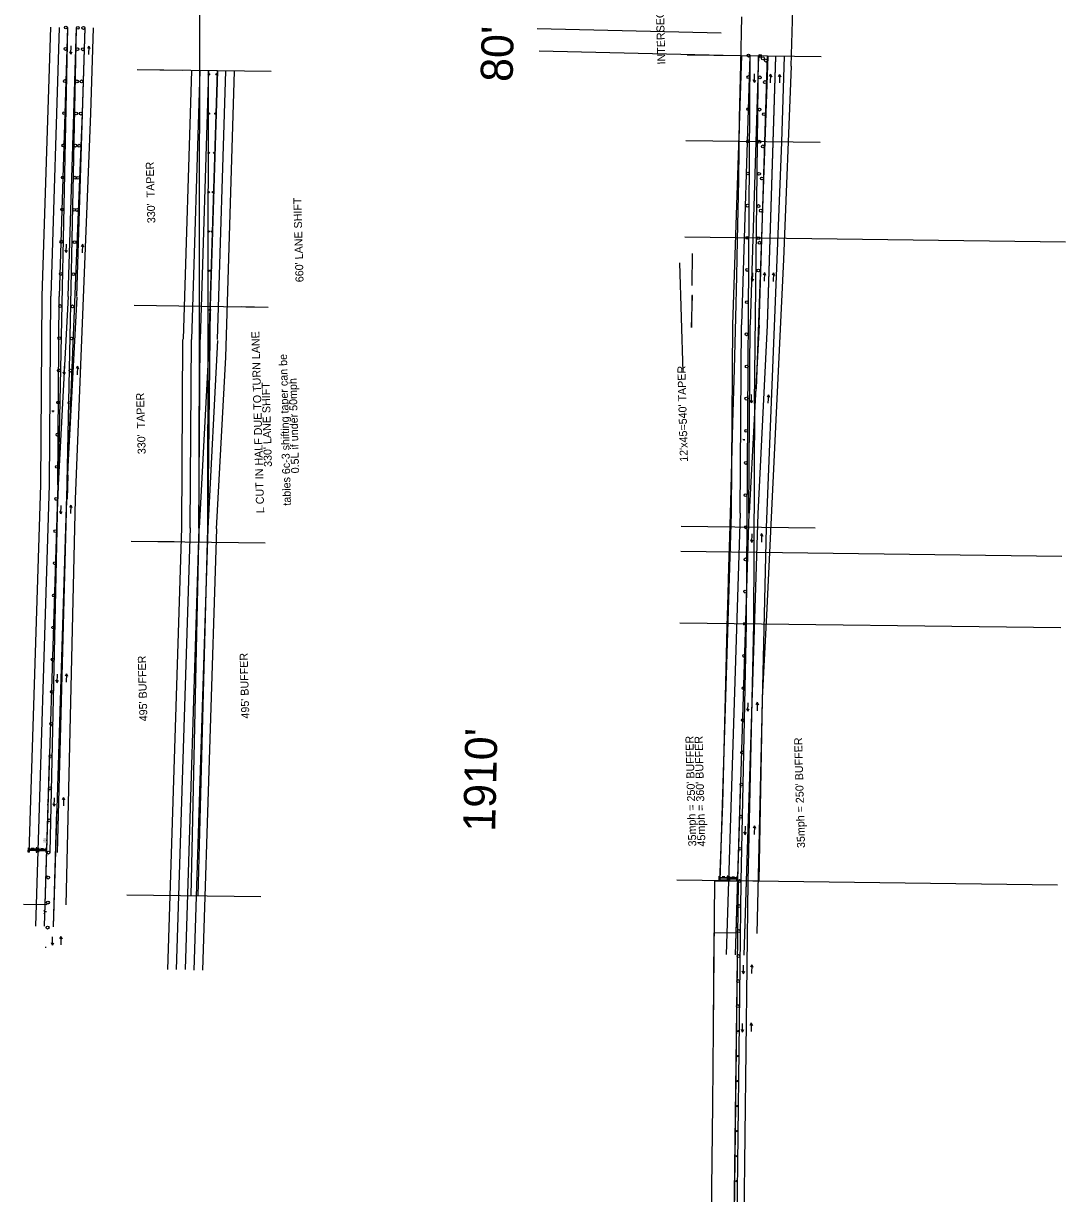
# Model space of a CAD drawing. Extents: x 1651568 to 1653044, y 601329 to 611807.
# Drawn here: x 1651568 to 1653027, y 608161 to 609799 of the extents above; entities that cross this region are included whole.
import ezdxf

# ---------------------------------------------------------------- set-up
doc = ezdxf.new("R2010")
doc.units = 0
for name, color, linetype in [('CM_Corridor_Design', 7, 'Continuous'), ('Default', 7, 'Continuous'), ('DR_X_Storm_Sewer', 7, 'Continuous'), ('DT_X_Break_Line', 7, 'Continuous'), ('DT_X_Contour_Major', 7, 'Continuous'), ('DT_X_Void', 7, 'Continuous'), ('GE_P_Alignment_500_Cardinal_Points', 7, 'Continuous'), ('GE_P_Alignment_500_Distances', 7, 'Continuous'), ('GE_P_Alignment_500_Stations', 7, 'Continuous'), ('PF_P_Grade_Line', 7, 'Continuous'), ('PF_X_Ground_Line', 7, 'Continuous'), ('PF_X_Ground_Line_LT', 7, 'Continuous'), ('PF_X_Ground_Line_RT', 7, 'Continuous'), ('PV_P_EOP', 7, 'Continuous'), ('PV_X_EOP', 7, 'Continuous'), ('RW_X_Esmt_LA', 7, 'Continuous'), ('SC_ProfileRun1', 7, 'Continuous'), ('SC_ProfileRun2', 7, 'Continuous'), ('SC_Scratch3', 7, 'Continuous')]:
    doc.layers.add(name, color=color, linetype=linetype)

msp = doc.modelspace()

# ---------------------------------------------------------------- linework, layer by layer
at = {"layer": 'CM_Corridor_Design'}
for p, q in [((1651634.4, 609755.7), (1651634.7, 609767.6)), ((1651659.4, 609767.2), (1651657.6, 609763.9)), ((1651659.4, 609767.2), (1651659, 609755.3)), ((1651659.4, 609767.2), (1651661, 609763.8)), ((1651634.4, 609755.7), (1651632.8, 609759.1)), ((1651634.4, 609755.7), (1651636.2, 609759)), ((1652591.3, 609716.3), (1652589.6, 609719.7)), ((1652591.3, 609716.3), (1652591.6, 609728.1)), ((1652591.3, 609716.3), (1652593.1, 609719.6)), ((1652613.9, 609727.8), (1652612.1, 609724.4)), ((1652613.9, 609727.8), (1652613.5, 609715.9)), ((1652613.9, 609727.8), (1652615.5, 609724.3)), ((1652626.5, 609727.4), (1652624.7, 609724)), ((1652626.5, 609727.4), (1652626.2, 609715.5)), ((1652626.5, 609727.4), (1652628.1, 609723.9)), ((1651627.9, 609478.2), (1651628.3, 609490)), ((1651650.7, 609489.7), (1651648.9, 609486.3)), ((1651650.7, 609489.7), (1651650.3, 609477.8)), ((1651650.7, 609489.7), (1651652.3, 609486.2)), ((1651627.9, 609478.2), (1651626.3, 609481.6)), ((1651627.9, 609478.2), (1651629.8, 609481.5)), ((1652588.7, 609438), (1652587, 609441.4)), ((1652588.7, 609438), (1652589, 609449.8)), ((1652588.7, 609438), (1652590.5, 609441.3)), ((1652605.3, 609450.1), (1652603.5, 609446.7)), ((1652605.3, 609450.1), (1652604.9, 609438.2)), ((1652605.3, 609450.1), (1652606.9, 609446.6)), ((1652617.9, 609449.7), (1652616.1, 609446.4)), ((1652617.9, 609449.7), (1652617.6, 609437.8)), ((1652617.9, 609449.7), (1652619.5, 609446.3)), ((1651625.1, 609307.3), (1651623.5, 609310.7)), ((1651625.1, 609307.3), (1651625.5, 609319.1)), ((1651625.1, 609307.3), (1651627, 609310.6)), ((1651643.8, 609319), (1651641.9, 609315.7)), ((1651643.8, 609319), (1651643.1, 609307.2)), ((1651643.8, 609319), (1651645.3, 609315.5)), ((1652587, 609267.8), (1652587.4, 609279.6)), ((1652611, 609279.2), (1652609, 609275.9)), ((1652611, 609279.2), (1652610.2, 609267.3)), ((1652611, 609279.2), (1652612.5, 609275.7)), ((1652587, 609267.8), (1652585.4, 609271.2)), ((1652587, 609267.8), (1652588.9, 609271.1)), ((1651620.6, 609112.4), (1651619, 609115.8)), ((1651620.6, 609112.4), (1651621, 609124.3)), ((1651620.6, 609112.4), (1651622.4, 609115.7)), ((1651634.2, 609124.6), (1651632.5, 609121.3)), ((1651634.2, 609124.6), (1651634.1, 609112.8)), ((1651634.2, 609124.6), (1651635.9, 609121.2)), ((1652587.8, 609072.6), (1652588.1, 609084.4)), ((1652601.4, 609084.8), (1652599.6, 609081.5)), ((1652601.4, 609084.8), (1652601.2, 609073)), ((1652601.4, 609084.8), (1652603.1, 609081.4)), ((1652587.8, 609072.6), (1652586.2, 609076)), ((1652587.8, 609072.6), (1652589.6, 609075.9)), ((1651615.2, 608876.1), (1651615.5, 608888)), ((1651628.1, 608888.5), (1651626.3, 608885.2)), ((1651628.1, 608888.5), (1651627.9, 608876.7)), ((1651628.1, 608888.5), (1651629.7, 608885.1)), ((1651615.2, 608876.1), (1651613.5, 608879.6)), ((1651615.2, 608876.1), (1651617, 608879.5)), ((1652582.3, 608836.3), (1652580.7, 608839.8)), ((1652582.3, 608836.3), (1652582.6, 608848.2)), ((1652582.3, 608836.3), (1652584.1, 608839.7)), ((1652595.2, 608848.7), (1652593.4, 608845.4)), ((1652595.2, 608848.7), (1652595.1, 608836.8)), ((1652595.2, 608848.7), (1652596.9, 608845.3)), ((1651611.1, 608703.3), (1651609.5, 608706.7)), ((1651611.1, 608703.3), (1651611.5, 608715.1)), ((1651611.1, 608703.3), (1651613, 608706.6)), ((1651624, 608715.6), (1651622.3, 608712.2)), ((1651624, 608715.6), (1651623.9, 608703.7)), ((1651624, 608715.6), (1651625.7, 608712.2)), ((1652578.3, 608663.4), (1652578.6, 608675.3)), ((1652591.2, 608675.8), (1652589.4, 608672.4)), ((1652591.2, 608675.8), (1652591.1, 608663.9)), ((1652591.2, 608675.8), (1652592.9, 608672.4)), ((1652578.3, 608663.4), (1652576.7, 608666.9)), ((1652578.3, 608663.4), (1652580.1, 608666.8)), ((1651608.8, 608508.7), (1651607.1, 608512.1)), ((1651608.8, 608508.7), (1651608.9, 608520.6)), ((1651608.8, 608508.7), (1651610.6, 608512.1)), ((1651620.4, 608521), (1651618.6, 608517.6)), ((1651620.4, 608521), (1651620.3, 608509.1)), ((1651620.4, 608521), (1651622.1, 608517.6)), ((1652576, 608468.9), (1652576.1, 608480.8)), ((1652587.5, 608481.1), (1652585.8, 608477.8)), ((1652587.5, 608481.1), (1652587.4, 608469.3)), ((1652587.5, 608481.1), (1652589.2, 608477.8)), ((1652576, 608468.9), (1652574.3, 608472.3)), ((1652576, 608468.9), (1652577.7, 608472.3)), ((1652574.7, 608387.2), (1652574.8, 608399.1)), ((1652586.9, 608399.9), (1652585.1, 608396.6)), ((1652586.9, 608399.9), (1652586.8, 608388)), ((1652586.9, 608399.9), (1652588.6, 608396.5)), ((1652574.7, 608387.2), (1652573, 608390.6)), ((1652574.7, 608387.2), (1652576.5, 608390.6))]:
    msp.add_line(p, q, dxfattribs=at)
at = {"layer": 'Default'}
for p, q in [((1652642.7, 609739.1), (1652645.7, 609834.8)), ((1652572.1, 609742), (1652573.5, 609808.2)), ((1652642.7, 609739.1), (1652632.1, 609468.6)), ((1652632.1, 609468.6), (1652608, 608970.7)), ((1652608, 608970.7), (1652602.3, 608854.3)), ((1652602.3, 608854.3), (1652597.5, 608598.3)), ((1652597.5, 608598.3), (1652542.8, 608598.9))]:
    msp.add_line(p, q, dxfattribs=at)
msp.add_lwpolyline([(1652542.8, 608598.9), (1652547, 608706.4), (1652549.3, 608800.4), (1652551.2, 608875.4), (1652553.2, 608954.6), (1652554.5, 609000.2), (1652555.6, 609038.2), (1652556.7, 609080.1), (1652558.2, 609129.4), (1652559.8, 609184.7), (1652561.2, 609239.6), (1652563.4, 609315.2), (1652565.1, 609387.4), (1652566.6, 609445.1), (1652567.6, 609495.4), (1652569.3, 609579.3), (1652570.5, 609666.4), (1652572.1, 609742)], dxfattribs=at)
at = {"layer": 'DR_X_Storm_Sewer'}
msp.add_line((1652609.8, 609376.4), (1652621.5, 609752.8), dxfattribs=at)
at = {"layer": 'DT_X_Break_Line'}
for centre, radius in [((1651627.4, 609793.2), 2), ((1651644.2, 609792.8), 2), ((1651651.9, 609792.6), 2), ((1651627, 609763.2), 2), ((1651643.5, 609762.8), 2), ((1651651.1, 609762.7), 2), ((1652583, 609753.8), 2), ((1652599.4, 609753.3), 2), ((1652603.2, 609750), 2), ((1652607.4, 609746.8), 2), ((1651625.9, 609718.2), 2), ((1651642.9, 609717.8), 2), ((1651649.4, 609717.7), 2), ((1651827.7, 609727.7), 1), ((1651838.6, 609727.6), 1), ((1652582.9, 609723.8), 2), ((1652598.9, 609723.3), 2), ((1652606.1, 609716.8), 2), ((1651625, 609673.2), 2), ((1651641.7, 609672.8), 2), ((1651648.2, 609672.7), 2), ((1651827.6, 609672.7), 1), ((1651836.9, 609672.7), 1), ((1652582.6, 609678.8), 2), ((1652598.5, 609678.3), 2), ((1652604.6, 609671.8), 2), ((1652582.3, 609633.8), 2), ((1651624, 609628.2), 2), ((1651640.8, 609627.9), 2), ((1651646.1, 609627.7), 2), ((1652598.1, 609633.3), 2), ((1652603.2, 609626.8), 2), ((1651827.5, 609617.7), 1), ((1651835.2, 609617.7), 1), ((1652582.1, 609588.8), 2), ((1652597.7, 609588.3), 2), ((1651623.1, 609583.2), 2), ((1651640, 609582.9), 2), ((1651644.5, 609582.8), 2), ((1652601.9, 609581.8), 2), ((1651827.4, 609562.7), 1), ((1651833.5, 609562.7), 1), ((1651622.2, 609538.3), 2), ((1651639, 609537.9), 2), ((1651642.9, 609537.8), 2), ((1652581.7, 609543.8), 2), ((1652597, 609543.3), 2), ((1652600.2, 609536.8), 2), ((1651827.3, 609507.7), 1), ((1651831.9, 609507.7), 1), ((1651621.2, 609493.3), 2), ((1651639.7, 609492.8), 2), ((1652581.5, 609498.7), 2), ((1652596.7, 609498.3), 2), ((1652598.5, 609491.9), 2), ((1652581.1, 609453.8), 2), ((1651620.3, 609448.3), 2), ((1651638, 609447.9), 2), ((1651827.2, 609452.7), 1), ((1651830.2, 609452.8), 1), ((1652596.8, 609453), 2), ((1652580.6, 609408.8), 2), ((1651619.4, 609403.3), 2), ((1651636.7, 609402.9), 2), ((1651829, 609397.8), 1), ((1651618.4, 609358.3), 2), ((1651635.4, 609357.9), 2), ((1652580.2, 609363.8), 2), ((1651827.9, 609342.8), 1), ((1651617.5, 609313.3), 2), ((1651634, 609312.9), 2), ((1652580.5, 609318.7), 2), ((1651827.3, 609287.8), 1), ((1652580.1, 609273.7), 2), ((1651616.6, 609268.3), 2), ((1651632.6, 609267.9), 2), ((1651826.8, 609232.8), 1), ((1652579.7, 609228.7), 2), ((1651615.7, 609223.3), 2), ((1651614.7, 609178.3), 2), ((1652579.3, 609183.7), 2), ((1651613.8, 609133.3), 2), ((1652578.9, 609138.7), 2), ((1652579.2, 609093.7), 2), ((1651612.8, 609088.3), 2), ((1652578.8, 609048.7), 2), ((1651611.9, 609043.3), 2), ((1651610.9, 608998.4), 2), ((1652578.3, 609003.6), 2), ((1651609.9, 608953.4), 2), ((1652577.9, 608958.6), 2), ((1652576.9, 608913.6), 2), ((1651609, 608908.4), 2), ((1652576.1, 608868.6), 2), ((1651608, 608863.4), 2), ((1651607, 608818.4), 2), ((1652575.1, 608823.6), 2), ((1651606, 608773.4), 2), ((1652574.2, 608778.6), 2), ((1652573.2, 608733.6), 2), ((1651605.1, 608728.4), 2), ((1652572.2, 608688.6), 2), ((1651604.1, 608683.4), 2), ((1651603.1, 608638.4), 2), ((1652571.3, 608643.6), 2), ((1651602.7, 608603.4), 2), ((1652570.3, 608598.6), 2), ((1651602.3, 608568.4), 2), ((1652569.9, 608563.6), 2), ((1651601.9, 608533.4), 2), ((1652569.4, 608528.6), 2), ((1652569, 608493.6), 2), ((1652568.6, 608458.6), 2), ((1652568.2, 608423.6), 2), ((1652568.8, 608388.6), 1), ((1652568.4, 608353.6), 1), ((1652568, 608318.6), 1), ((1652567.6, 608283.6), 1), ((1652567.1, 608248.6), 1), ((1652566.7, 608213.6), 1), ((1652566.3, 608178.6), 1)]:
    msp.add_circle(centre, radius, dxfattribs=at)
at = {"layer": 'DT_X_Contour_Major'}
for p, q in [((1651600.7, 608565.3), (1651568, 608565.7)), ((1652567.8, 608525.5), (1652535.1, 608525.9)), ((1652551.8, 607199.3), (1652567.4, 608491.6))]:
    msp.add_line(p, q, dxfattribs=at)
for points in [[(1652520.5, 607302), (1652521, 607315.7), (1652521, 607315.6), (1652521.1, 607315.9), (1652521, 607315.7), (1652522, 607405.3), (1652522, 607405.3), (1652523.6, 607497.3), (1652523.6, 607516), (1652525.3, 607645.8), (1652525.5, 607668.5), (1652527.1, 607790.4), (1652527.1, 607790.4), (1652529.5, 607988.1), (1652531.2, 608129.7), (1652532.9, 608285.7), (1652534.2, 608392.3), (1652536.1, 608599), (1652568.7, 608598.6), (1652551.8, 607199.3), (1652540, 606229.1)], [(1652520.5, 607302), (1652521, 607315.7), (1652521, 607315.6), (1652521.1, 607315.9), (1652521, 607315.7), (1652522, 607405.3), (1652522, 607405.3), (1652523.6, 607497.3), (1652523.6, 607516), (1652525.3, 607645.8), (1652525.5, 607668.5), (1652527.1, 607790.4), (1652527.1, 607790.4), (1652529.5, 607988.1), (1652531.2, 608129.7), (1652532.9, 608285.7), (1652534.2, 608392.3), (1652536.1, 608599), (1652568.7, 608598.6), (1652551.8, 607199.3), (1652540, 606229.1)], [(1652527.1, 607790.4), (1652529.5, 607988.1), (1652531.2, 608129.7), (1652532.9, 608285.7), (1652534.2, 608392.3), (1652535.1, 608525.9)]]:
    msp.add_lwpolyline(points, dxfattribs=at)
at = {"layer": 'DT_X_Void'}
for p, q in [((1651585.9, 608643.1), (1651575.9, 608643.2)), ((1651585.9, 608641.1), (1651575.9, 608641.2)), ((1651578.9, 608644.6), (1651582.9, 608644.6)), ((1651579.9, 608643.1), (1651579.9, 608644.6)), ((1651580.9, 608642.1), (1651580.9, 608642.1)), ((1651581.9, 608643.1), (1651581.9, 608644.6)), ((1651599.3, 608642.8), (1651589.3, 608642.9)), ((1651599.3, 608640.8), (1651589.3, 608640.9)), ((1651592.3, 608644.4), (1651596.3, 608644.3)), ((1651593.3, 608642.9), (1651593.3, 608644.4)), ((1651594.3, 608641.9), (1651594.3, 608641.9)), ((1651595.3, 608642.8), (1651595.3, 608644.3)), ((1652546.1, 608604.8), (1652550.1, 608604.8)), ((1652547.1, 608603.3), (1652547.1, 608604.8)), ((1652549.1, 608603.3), (1652549.1, 608604.8)), ((1652559.5, 608604.6), (1652563.5, 608604.5)), ((1652560.5, 608603.1), (1652560.5, 608604.6)), ((1652562.5, 608603), (1652562.5, 608604.5)), ((1652553.1, 608603.2), (1652543.1, 608603.4)), ((1652553.1, 608601.2), (1652543.1, 608601.4)), ((1652548.1, 608602.3), (1652548.1, 608602.3)), ((1652566.4, 608601), (1652556.4, 608601.1)), ((1652566.5, 608603), (1652556.5, 608603.1)), ((1652561.4, 608602), (1652561.4, 608602))]:
    msp.add_line(p, q, dxfattribs=at)
for points in [[(1651574.9, 608639.2), (1651575, 608645.2), (1651576, 608645.2), (1651575.9, 608639.2)], [(1651586.9, 608639), (1651587, 608645), (1651586, 608645.1), (1651585.9, 608639.1)], [(1651588.3, 608638.9), (1651588.3, 608644.9), (1651589.3, 608644.9), (1651589.3, 608638.9)], [(1651600.3, 608638.8), (1651600.3, 608644.8), (1651599.3, 608644.8), (1651599.3, 608638.8)], [(1652542, 608599.4), (1652542.1, 608605.4), (1652543.1, 608605.4), (1652543, 608599.4)], [(1652554, 608599.2), (1652554.1, 608605.2), (1652553.1, 608605.2), (1652553, 608599.2)], [(1652555.4, 608599.1), (1652555.5, 608605.1), (1652556.5, 608605.1), (1652556.4, 608599.1)], [(1652567.4, 608599), (1652567.5, 608605), (1652566.5, 608605), (1652566.4, 608599)]]:
    msp.add_lwpolyline(points, close=True, dxfattribs=at)
at = {"layer": 'GE_P_Alignment_500_Cardinal_Points'}
for p, q in [((1652544.8, 609785.2), (1652287.4, 609791.2)), ((1652547.7, 609754), (1652290.2, 609760)), ((1651790.9, 609733), (1651727.1, 609733.8)), ((1653026.9, 609492.9), (1652493.8, 609499.6)), ((1652504.3, 609477), (1652503.9, 609432)), ((1652503.6, 609418.1), (1652503.3, 609373.1)), ((1652503.3, 609373.1), (1652504.6, 609418)), ((1652504.6, 609418), (1652503.6, 609418.1)), ((1651779, 609073.1), (1651718.8, 609073.9)), ((1653021.4, 609053), (1652488.3, 609059.7)), ((1653020.1, 608953), (1652487, 608959.7)), ((1653015.6, 608593), (1652482.5, 608599.7)), ((1651900.3, 608576.6), (1651712.6, 608578.9))]:
    msp.add_line(p, q, dxfattribs=at)
at = {"layer": 'GE_P_Alignment_500_Distances'}
for p, q in [((1652684.6, 609752.2), (1652497, 609754.6)), ((1651914.8, 609731.5), (1651727.1, 609733.8)), ((1652683.1, 609632.3), (1652495.5, 609634.6)), ((1652491.6, 609310.7), (1652487.1, 609463.6)), ((1651910.6, 609401.5), (1651723, 609403.9)), ((1651910.6, 609401.5), (1651872.9, 609402)), ((1652676.4, 609092.3), (1652488.7, 609094.7)), ((1651906.5, 609071.5), (1651718.8, 609073.9))]:
    msp.add_line(p, q, dxfattribs=at)
at = {"layer": 'GE_P_Alignment_500_Stations'}
for p, q in [((1651602.3, 608705.4), (1651601.1, 608705.4)), ((1651601.7, 608655.4), (1651599.7, 608655.4)), ((1651601.1, 608605.4), (1651599.9, 608605.4)), ((1651600.5, 608555.4), (1651598.5, 608555.4)), ((1651599.9, 608505.4), (1651598.7, 608505.4))]:
    msp.add_line(p, q, dxfattribs=at)
at = {"layer": 'PF_P_Grade_Line'}
for p, q in [((1651594.2, 609417.1), (1651606.3, 609793.5)), ((1651662.6, 609672.7), (1651666.3, 609792.7)), ((1652561.3, 609377.3), (1652573.5, 609753.6)), ((1652629.7, 609632.9), (1652633.5, 609752.9)), ((1651791.9, 609357.1), (1651803.6, 609732.9)), ((1651851.2, 609331.8), (1651863.6, 609732.1)), ((1651640.8, 609133), (1651662.6, 609672.7)), ((1652608, 609093.2), (1652629.7, 609632.9)), ((1651592.3, 609153.3), (1651594.2, 609417.1)), ((1652559.4, 609113.5), (1652561.3, 609377.3)), ((1651789.6, 609092.7), (1651791.4, 609356.5)), ((1651838.5, 609091.3), (1651851.2, 609331.8)), ((1651576.2, 608638.7), (1651592.3, 609153.3)), ((1651627.9, 608565.1), (1651640.8, 609133)), ((1652543.4, 608598.9), (1652559.4, 609113.5)), ((1651770.3, 608474.9), (1651789.6, 609092.7)), ((1651819.2, 608473.7), (1651838.6, 609091.5)), ((1652595.1, 608525.3), (1652608, 609093.2))]:
    msp.add_line(p, q, dxfattribs=at)
at = {"layer": 'PF_X_Ground_Line'}
for p, q in [((1651607.8, 609256.6), (1651611, 609256.5)), ((1651609.4, 609256.6), (1651609.4, 609255)), ((1651609.4, 609256.6), (1651609.4, 609256.6)), ((1652574.9, 609216.8), (1652578.1, 609216.7)), ((1652576.5, 609216.8), (1652576.5, 609215.2)), ((1652576.5, 609216.8), (1652576.5, 609216.8))]:
    msp.add_line(p, q, dxfattribs=at)
at = {"layer": 'PF_X_Ground_Line_LT'}
for p, q in [((1651616.3, 609153.1), (1651618.2, 609416.9)), ((1651617.3, 609153.1), (1651631.1, 609416.5)), ((1652583.4, 609113.3), (1652585.3, 609377.1)), ((1652584.4, 609113.3), (1652598.3, 609376.7)), ((1651813.6, 609092.6), (1651815.4, 609356.4)), ((1651814.6, 609092.5), (1651828.4, 609356)), ((1651597.5, 608535.2), (1651616.8, 609153.1)), ((1652564.6, 608495.4), (1652583.9, 609113.3)), ((1651794.8, 608474.7), (1651814.1, 609092.5)), ((1651597.5, 608535.2), (1651605.2, 608783.3)), ((1652564.6, 608495.4), (1652572.4, 608743.5))]:
    msp.add_line(p, q, dxfattribs=at)
at = {"layer": 'PF_X_Ground_Line_RT'}
for p, q in [((1651606.7, 609417.3), (1651618.3, 609793.3)), ((1651642.7, 609416.9), (1651654.3, 609792.9)), ((1652573.8, 609377.5), (1652585.5, 609753.5)), ((1652609.8, 609377.1), (1652621.5, 609753)), ((1651803.9, 609356.7), (1651815.6, 609732.7)), ((1651839.9, 609356.3), (1651851.6, 609732.3)), ((1651604.3, 609153.2), (1651606.2, 609417)), ((1651606.7, 609417), (1651606.7, 609417.3)), ((1651629.3, 609152.5), (1651643.1, 609415.9)), ((1652571.4, 609113.4), (1652573.3, 609377.2)), ((1652573.8, 609377.2), (1652573.8, 609377.5)), ((1652596.4, 609112.7), (1652609.8, 609376.4)), ((1651801.6, 609092.6), (1651803.4, 609356.4)), ((1651803.9, 609356.4), (1651803.9, 609356.7)), ((1651826.6, 609091.9), (1651840.4, 609355.3)), ((1651585.2, 608535.5), (1651604.5, 609153.3)), ((1651610, 608534.6), (1651629.3, 609152.5)), ((1652552.4, 608495.7), (1652571.7, 609113.5)), ((1652577.1, 608494.8), (1652596.4, 609112.7)), ((1651782.5, 608474.9), (1651801.8, 609092.8)), ((1651807.2, 608474), (1651826.6, 609091.9)), ((1651610, 608534.9), (1651615, 608697)), ((1652577.1, 608495), (1652582.2, 608657.2))]:
    msp.add_line(p, q, dxfattribs=at)
at = {"layer": 'PV_P_EOP'}
for p, q in [((1651815.1, 610062.8), (1651813.5, 609072.7)), ((1651629.8, 609793.2), (1651616.2, 609133.3)), ((1652580.4, 608958.5), (1652585.5, 609753.5)), ((1651605.5, 608638.4), (1651616.2, 609133.3)), ((1651802.8, 608577.8), (1651813.5, 609072.7)), ((1652572.7, 608598.6), (1652580.4, 608958.5)), ((1652557, 607300.8), (1652572.7, 608598.6))]:
    msp.add_line(p, q, dxfattribs=at)
at = {"layer": 'PV_X_EOP'}
for p, q in [((1652590.4, 608958.4), (1652591.7, 609266.7)), ((1651615.5, 608638.3), (1651628.8, 609133.1)), ((1652582.7, 608598.3), (1652590.4, 608958.4)), ((1652567, 607300.7), (1652582.7, 608598.4))]:
    msp.add_line(p, q, dxfattribs=at)
at = {"layer": 'RW_X_Esmt_LA'}
for p, q in [((1651641.8, 609792.9), (1651628.3, 609133.1)), ((1651650.6, 609673.1), (1651654.3, 609793.1)), ((1652591.2, 609266.7), (1652597, 609753.4)), ((1652610, 609753.2), (1652593.8, 609287.6)), ((1651826.5, 609732.6), (1651825.5, 609072.7)), ((1651829.9, 609402.5), (1651840.1, 609732.4)), ((1651630.2, 609166.4), (1651650.6, 609673.2)), ((1651826.1, 609072.6), (1651829.9, 609402.5)), ((1652592.2, 609266.7), (1652593.8, 609287.6)), ((1651630.2, 609166.4), (1651629.3, 609133.1)), ((1651812.8, 608577.7), (1651826.1, 609091.9))]:
    msp.add_line(p, q, dxfattribs=at)
at = {"layer": 'SC_ProfileRun1'}
for p, q in [((1651630.6, 609416.5), (1651642.3, 609793)), ((1652597.8, 609376.7), (1652609.5, 609753.2)), ((1651827.9, 609356), (1651839.6, 609732.4))]:
    msp.add_line(p, q, dxfattribs=at)
at = {"layer": 'SC_ProfileRun2'}
for p, q in [((1651618.7, 609416.9), (1651630.3, 609793.2)), ((1652585.8, 609377.1), (1652597.5, 609753.3)), ((1651815.9, 609356.3), (1651827.6, 609732.6))]:
    msp.add_line(p, q, dxfattribs=at)

# ---------------------------------------------------------------- texts
at = {"layer": 'GE_P_Alignment_500_Cardinal_Points'}
for s, p in [('INTERSECTION', (1652466.7, 609741.6)), ("330'  TAPER", (1651752.7, 609519.4)), ("660' LANE SHIFT", (1651960.2, 609436.8)), ('L CUT IN HALF DUE TO TURN LANE', (1651905.1, 609113.6)), ('tables 6c-3 shifting taper can be', (1651942.6, 609124.1)), ("12'x45=540' TAPER", (1652498.2, 609185.5)), ("330' LANE SHIFT", (1651915.9, 609178.3)), (' 0.5L if under 50mph', (1651954.1, 609165.2)), ("330'  TAPER", (1651739.2, 609196.1)), ("495' BUFFER", (1651884.3, 608826.1)), ("495' BUFFER", (1651741.7, 608822.3)), ("35mph = 250' BUFFER", (1652510, 608647.2)), ("45mph = 360' BUFFER", (1652522.8, 608647)), ("35mph = 250' BUFFER", (1652662.2, 608644.9))]:
    msp.add_text(s, height=11.2, rotation=91.5443, dxfattribs=at).set_placement(p)
at = {"layer": 'GE_P_Alignment_500_Stations'}
for s, p in [('126', (1651599.2, 608652.1)), ('125', (1651598, 608552.1))]:
    msp.add_text(s, height=2.8, rotation=89.3076, dxfattribs=at).set_placement(p)
at = {"layer": 'SC_Scratch3'}
for s, p in [("80'", (1652252.7, 609716.7)), ("1910'", (1652228.3, 608667.2))]:
    msp.add_text(s, height=44.8, rotation=88.672, dxfattribs=at).set_placement(p)

doc.saveas('drawing.dxf')
